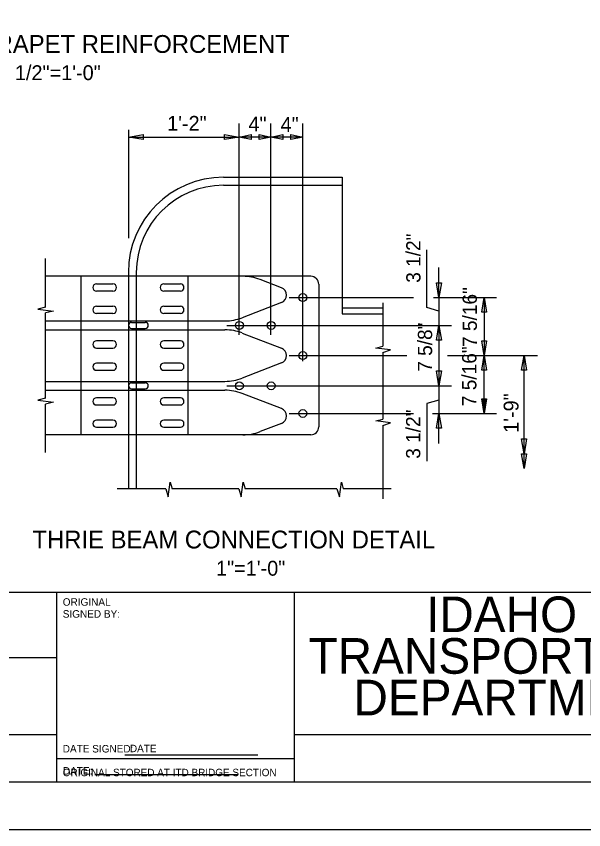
# Model space of a CAD drawing. Extents: x 0 to 68, y 0 to 47.1.
# Drawn here: x 22.15 to 34.08, y 0 to 17.11 of the extents above; entities that cross this region are included whole.
import ezdxf

# ---------------------------------------------------------------- set-up
doc = ezdxf.new("R2010")
doc.units = 0
for name, color, linetype in [('BORDER_ANNO_Cutsheet', 7, 'Continuous'), ('BRDG_ANNO_Anno-Large-Print', 7, 'Continuous'), ('BRDG_ANNO_Anno-Sheet', 7, 'Continuous'), ('BRDG_ANNO_Anno-Small-Print', 7, 'Continuous'), ('BRDG_ANNO_General-Notes', 7, 'Continuous'), ('BRDG_BASE_Dtlctrln', 7, 'Continuous'), ('BRDG_BASE_Hidden-Line', 7, 'Continuous'), ('BRDG_BASE_Obj-Line', 7, 'Continuous'), ('BRDG_BASE_Rebar', 7, 'Continuous')]:
    doc.layers.add(name, color=color, linetype=linetype)

msp = doc.modelspace()

# ---------------------------------------------------------------- linework, layer by layer
at = {"layer": 'BORDER_ANNO_Cutsheet'}
msp.add_lwpolyline([(0, 44), (68, 44), (68, 0), (0, 0)], close=True, dxfattribs=at)
at = {"layer": 'BRDG_ANNO_Anno-Large-Print'}
msp.add_line((23.799, 1.161), (26.811, 1.161), dxfattribs=at)
at = {"layer": 'BRDG_ANNO_Anno-Sheet'}
for p, q in [((3, 5), (38.5, 5)), ((23, 1), (23, 5)), ((28, 1), (28, 5)), ((19, 3.625), (23, 3.625)), ((19, 2), (23, 2)), ((28, 2), (38.5, 2))]:
    msp.add_line(p, q, dxfattribs=at)
msp.add_lwpolyline([(3, 43), (67, 43), (67, 1), (3, 1)], close=True, dxfattribs=at)
at = {"layer": 'BRDG_ANNO_Anno-Small-Print'}
for p, q in [((24.432, 1.573), (27.227, 1.573)), ((23, 1.5), (28, 1.5))]:
    msp.add_line(p, q, dxfattribs=at)
at = {"layer": 'BRDG_ANNO_General-Notes'}
for p, q in [((24.505, 14.724), (24.505, 12.443)), ((24.505, 14.571), (24.815, 14.623)), ((24.505, 14.571), (26.839, 14.571)), ((24.815, 14.519), (24.505, 14.571)), ((24.815, 14.623), (24.815, 14.519)), ((26.529, 14.519), (26.529, 14.623)), ((26.529, 14.623), (26.839, 14.571)), ((26.839, 14.571), (26.529, 14.519)), ((26.839, 14.571), (27.09, 14.623)), ((27.505, 14.571), (26.839, 14.571)), ((27.09, 14.519), (26.839, 14.571)), ((27.09, 14.623), (27.09, 14.519)), ((27.254, 14.519), (27.254, 14.623)), ((27.254, 14.623), (27.505, 14.571)), ((27.505, 14.571), (27.254, 14.519)), ((27.505, 14.571), (27.756, 14.623)), ((28.172, 14.571), (27.505, 14.571)), ((27.756, 14.519), (27.505, 14.571)), ((27.756, 14.623), (27.756, 14.519)), ((27.921, 14.519), (27.921, 14.623)), ((27.921, 14.623), (28.172, 14.571)), ((28.172, 14.571), (27.921, 14.519)), ((30.781, 10.985), (30.781, 12.199)), ((31.037, 11.194), (31.037, 11.826)), ((30.986, 11.504), (31.089, 11.504)), ((31.037, 11.194), (30.986, 11.504)), ((31.089, 11.504), (31.037, 11.194)), ((31.037, 11.194), (31.037, 10.61)), ((31.936, 10.884), (31.987, 11.194)), ((31.987, 11.194), (31.987, 9.975)), ((31.987, 11.194), (32.039, 10.884)), ((31.037, 10.911), (30.781, 10.985)), ((32.039, 10.884), (31.936, 10.884)), ((30.986, 10.3), (31.037, 10.61)), ((31.037, 10.61), (31.037, 9.34)), ((31.037, 10.61), (31.089, 10.3)), ((31.089, 10.3), (30.986, 10.3)), ((31.936, 10.285), (32.039, 10.285)), ((31.987, 9.975), (31.936, 10.285)), ((32.039, 10.285), (31.987, 9.975)), ((31.936, 9.665), (31.987, 9.975)), ((31.987, 8.756), (31.987, 9.975)), ((31.987, 9.975), (32.039, 9.665)), ((32.775, 9.665), (32.827, 9.975)), ((32.827, 7.597), (32.827, 9.975)), ((32.827, 9.975), (32.878, 9.665)), ((30.986, 9.65), (31.089, 9.65)), ((31.037, 9.34), (30.986, 9.65)), ((31.089, 9.65), (31.037, 9.34)), ((32.039, 9.665), (31.936, 9.665)), ((32.878, 9.665), (32.775, 9.665)), ((31.037, 9.34), (31.037, 8.756)), ((31.037, 9.039), (30.781, 8.965)), ((30.781, 8.965), (30.781, 7.75)), ((31.947, 9.058), (31.981, 8.85)), ((31.959, 9.058), (31.98, 8.927)), ((31.973, 9.057), (31.98, 8.981)), ((32.028, 9.058), (31.994, 8.85)), ((32.016, 9.058), (31.995, 8.927)), ((32.002, 9.057), (31.995, 8.981)), ((30.986, 8.446), (31.037, 8.756)), ((31.037, 8.124), (31.037, 8.756)), ((31.037, 8.756), (31.089, 8.446)), ((31.089, 8.446), (30.986, 8.446)), ((32.775, 8.22), (32.878, 8.22)), ((32.827, 7.91), (32.775, 8.22)), ((32.878, 8.22), (32.827, 7.91)), ((32.775, 7.907), (32.878, 7.907)), ((32.827, 7.597), (32.775, 7.907)), ((32.878, 7.907), (32.827, 7.597))]:
    msp.add_line(p, q, dxfattribs=at)
msp.add_lwpolyline([(32.039, 9.066), (31.987, 8.756), (31.936, 9.066)], close=True, dxfattribs=at)
at = {"layer": 'BRDG_BASE_Dtlctrln'}
for p, q in [((26.839, 10.407), (26.839, 14.853)), ((27.505, 10.407), (27.505, 14.853)), ((28.172, 9.854), (28.172, 14.853)), ((27.888, 11.194), (30.502, 11.194)), ((30.921, 11.194), (32.251, 11.194)), ((26.579, 10.61), (31.3, 10.61)), ((27.888, 9.975), (30.359, 9.975)), ((31.218, 9.975), (33.108, 9.975)), ((26.579, 9.34), (31.3, 9.34)), ((27.888, 8.756), (30.502, 8.756)), ((30.901, 8.756), (32.251, 8.756))]:
    msp.add_line(p, q, dxfattribs=at)
at = {"layer": 'BRDG_BASE_Hidden-Line'}
for p, q in [((23.508, 11.641), (23.508, 8.307)), ((24.505, 11.642), (24.505, 8.308)), ((24.672, 11.641), (24.672, 8.308))]:
    msp.add_line(p, q, dxfattribs=at)
at = {"layer": 'BRDG_BASE_Obj-Line'}
for p, q in [((26.505, 13.724), (29.005, 13.724)), ((29.005, 13.724), (29.005, 10.85)), ((26.505, 13.558), (29.005, 13.558)), ((22.766, 10.995), (22.766, 12.016)), ((28.341, 11.641), (22.766, 11.641)), ((24.505, 11.724), (24.505, 11.641)), ((24.672, 11.724), (24.672, 11.641)), ((25.758, 11.641), (25.758, 8.307)), ((27.723, 11.4), (27.275, 11.573)), ((28.508, 11.474), (28.508, 8.474)), ((22.766, 10.995), (22.599, 10.953)), ((22.599, 10.953), (22.932, 10.911)), ((27.723, 11.089), (26.897, 10.77)), ((29.005, 10.975), (29.858, 10.975)), ((29.858, 11.081), (29.858, 10.174)), ((22.932, 10.911), (22.766, 10.87)), ((22.766, 9.078), (22.766, 10.87)), ((29.005, 10.85), (29.858, 10.85)), ((22.766, 10.703), (26.537, 10.703)), ((22.766, 10.516), (26.537, 10.516)), ((26.897, 10.448), (27.723, 10.129)), ((29.713, 10.133), (29.858, 10.174)), ((30.02, 10.093), (29.713, 10.133)), ((29.858, 10.04), (30.02, 10.093)), ((29.858, 10.04), (29.858, 8.639)), ((27.723, 9.818), (26.897, 9.499)), ((22.766, 9.432), (26.537, 9.432)), ((22.766, 9.245), (26.537, 9.245)), ((22.766, 9.078), (22.599, 9.036)), ((27.723, 8.859), (26.897, 9.178)), ((22.599, 9.036), (22.932, 8.995)), ((22.932, 8.995), (22.766, 8.953)), ((22.766, 7.932), (22.766, 8.953)), ((29.713, 8.598), (29.858, 8.639)), ((30.02, 8.556), (29.713, 8.598)), ((29.858, 8.504), (30.02, 8.556)), ((27.723, 8.548), (27.275, 8.374)), ((29.858, 8.504), (29.858, 6.961)), ((28.341, 8.307), (22.766, 8.307)), ((24.505, 8.308), (24.505, 7.168)), ((24.672, 8.308), (24.672, 7.168)), ((25.343, 7.005), (25.385, 7.313)), ((25.385, 7.313), (25.426, 7.168)), ((26.88, 7.005), (26.92, 7.313)), ((26.92, 7.313), (26.961, 7.168)), ((28.943, 7.005), (28.985, 7.313)), ((28.985, 7.313), (29.026, 7.168)), ((25.291, 7.168), (24.268, 7.168)), ((25.291, 7.168), (25.343, 7.005)), ((26.827, 7.168), (25.426, 7.168)), ((26.827, 7.168), (26.88, 7.005)), ((27.868, 7.168), (26.961, 7.168)), ((28.891, 7.168), (27.868, 7.168)), ((28.891, 7.168), (28.943, 7.005)), ((30.033, 7.168), (29.026, 7.168))]:
    msp.add_line(p, q, dxfattribs=at)
for centre, radius, start, end in [((26.505, 11.724), 2, 90, 180), ((26.505, 11.724), 1.833, 90, 180), ((26.914, 10.641), 1, 68.8925, 90), ((28.341, 11.474), 0.167, 0, 90), ((27.663, 11.245), 0.167, 291.1197, 68.884), ((26.537, 11.703), 1, 270, 291.1068), ((26.537, 9.516), 1, 68.9012, 90), ((27.663, 9.974), 0.167, 291.1163, 68.88), ((26.537, 10.432), 1, 270, 291.1196), ((26.537, 8.245), 1, 68.8932, 90), ((27.663, 8.703), 0.167, 291.116, 68.8803), ((28.341, 8.474), 0.167, 270, 360), ((26.914, 9.307), 1, 270, 291.1075)]:
    msp.add_arc(centre, radius, start, end, dxfattribs=at)
at = {"layer": 'BRDG_BASE_Rebar'}
for p, q in [((23.833, 11.482), (24.182, 11.482)), ((25.25, 11.482), (25.599, 11.482)), ((24.182, 11.331), (23.833, 11.331)), ((25.599, 11.331), (25.25, 11.331)), ((23.833, 11.013), (24.182, 11.013)), ((25.25, 11.013), (25.599, 11.013)), ((24.182, 10.862), (23.833, 10.862)), ((25.599, 10.862), (25.25, 10.862)), ((24.57, 10.672), (24.862, 10.672)), ((24.57, 10.547), (24.862, 10.547)), ((24.182, 10.284), (23.833, 10.284)), ((25.599, 10.284), (25.25, 10.284)), ((23.833, 10.133), (24.182, 10.133)), ((25.25, 10.133), (25.599, 10.133)), ((24.182, 9.815), (23.833, 9.815)), ((25.599, 9.815), (25.25, 9.815)), ((23.833, 9.664), (24.182, 9.664)), ((25.25, 9.664), (25.599, 9.664)), ((24.57, 9.401), (24.862, 9.401)), ((24.57, 9.276), (24.862, 9.276)), ((24.182, 9.086), (23.833, 9.086)), ((25.599, 9.086), (25.25, 9.086)), ((23.833, 8.935), (24.182, 8.935)), ((25.25, 8.935), (25.599, 8.935)), ((24.182, 8.617), (23.833, 8.617)), ((25.599, 8.617), (25.25, 8.617)), ((23.833, 8.466), (24.182, 8.466)), ((25.25, 8.466), (25.599, 8.466))]:
    msp.add_line(p, q, dxfattribs=at)
for centre in [(28.174, 11.193), (26.841, 10.609), (27.508, 10.609), (28.174, 9.974), (26.841, 9.338), (27.508, 9.338), (28.174, 8.755)]:
    msp.add_circle(centre, 0.0833, dxfattribs=at)
for centre, radius, start, end in [((23.833, 11.406), 0.0755, 90, 270), ((24.182, 11.406), 0.0755, 270, 90), ((25.25, 11.406), 0.0755, 90, 270), ((25.599, 11.406), 0.0755, 270, 90), ((23.833, 10.937), 0.0755, 90, 270), ((24.182, 10.937), 0.0755, 270, 90), ((25.25, 10.937), 0.0755, 90, 270), ((25.599, 10.937), 0.0755, 270, 90), ((24.57, 10.609), 0.0625, 90, 270), ((24.862, 10.609), 0.0625, 270, 90), ((23.833, 10.208), 0.0755, 90, 270), ((24.182, 10.208), 0.0755, 270, 90), ((25.25, 10.208), 0.0755, 90, 270), ((25.599, 10.208), 0.0755, 270, 90), ((23.833, 9.74), 0.0755, 90, 270), ((24.182, 9.74), 0.0755, 270, 90), ((25.25, 9.74), 0.0755, 90, 270), ((25.599, 9.74), 0.0755, 270, 90), ((24.57, 9.338), 0.0625, 90, 270), ((24.862, 9.338), 0.0625, 270, 90), ((23.833, 9.01), 0.0755, 90, 270), ((24.182, 9.01), 0.0755, 270, 90), ((25.25, 9.01), 0.0755, 90, 270), ((25.599, 9.01), 0.0755, 270, 90), ((23.833, 8.542), 0.0755, 90, 270), ((24.182, 8.542), 0.0755, 270, 90), ((25.25, 8.542), 0.0755, 90, 270), ((25.599, 8.542), 0.0755, 270, 90)]:
    msp.add_arc(centre, radius, start, end, dxfattribs=at)

# ---------------------------------------------------------------- texts
at = {"layer": 'BRDG_ANNO_Anno-Large-Print'}
msp.add_text('DATE:', height=0.1574, dxfattribs=at).set_placement((23.13, 1.161))
at = {"layer": 'BRDG_ANNO_Anno-Sheet'}
for s, p in [('IDAHO', (30.767, 4.156)), ('TRANSPORTATION', (28.294, 3.281)), ('DEPARTMENT', (29.239, 2.406))]:
    msp.add_text(s, height=0.75, dxfattribs=at).set_placement(p)
at = {"layer": 'BRDG_ANNO_Anno-Small-Print'}
for s, height, p in [('ORIGINAL', 0.1575, (23.125, 4.712)), ('SIGNED BY:', 0.1575, (23.125, 4.461)), ('DATE SIGNED:', 0.1575, (23.125, 1.625)), ('DATE', 0.1574, (24.537, 1.631)), ('ORIGINAL STORED AT ITD BRIDGE SECTION', 0.15643, (23.125, 1.126))]:
    msp.add_text(s, height=height, dxfattribs=at).set_placement(p)
at = {"layer": 'BRDG_ANNO_General-Notes'}
for s, height, p in [('ELEVATION OF PARAPET REINFORCEMENT', 0.375, (17.255, 16.341)), ('1/2"=1\'-0"', 0.3125, (22.119, 15.768)), ('1\'-2"', 0.3125, (25.32, 14.703)), ('4"', 0.3125, (27.031, 14.69)), ('4"', 0.3125, (27.707, 14.679)), ('THRIE BEAM CONNECTION DETAIL', 0.375, (22.488, 5.917)), ('1"=1\'-0"', 0.3125, (26.349, 5.344))]:
    msp.add_text(s, height=height, dxfattribs=at).set_placement(p)
for s, height, p in [('3 1/2"', 0.3, (30.649, 11.505)), ('7 5/16"', 0.3, (31.835, 10.155)), ('7 5/8"', 0.3, (30.894, 9.633)), ('7 5/16"', 0.3, (31.825, 8.91)), ('1\'-9"', 0.3125, (32.711, 8.348)), ('3 1/2"', 0.3, (30.645, 7.803))]:
    msp.add_text(s, height=height, rotation=90, dxfattribs=at).set_placement(p)

doc.saveas('drawing.dxf')
